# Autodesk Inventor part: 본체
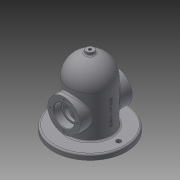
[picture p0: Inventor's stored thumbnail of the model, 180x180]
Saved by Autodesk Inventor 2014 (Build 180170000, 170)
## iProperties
Created: 2019-11
Part Number: 본체
Material: Generic
Document SubType Name: Modeling
Designer: OA55
Density: 1 g/cm^3
Appearance: Default
Author: OA55
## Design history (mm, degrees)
sketch "스케치1"
  geometry: C1 r 40 at (0, 0); 1 further point
  constraints: 1 centre point, 1 coincident
  dimensions: "d0" = 80 diameter of C1
extrude "돌출1" new body sketch "스케치1" distance "d1" = 80; taper "d2" = 0 deg
sketch "스케치2"
  geometry: C1 r 40 at (0, 0) reference; C2 r 70 at (0, 0)
  constraints: 1 centre point, 1 coincident
  dimensions: "d3" = 140 diameter of C2
extrude "돌출2" join sketch "스케치2" distance "d4" = 10; taper "d5" = 0 deg
node "작업 평면1"
sketch "스케치3"
  geometry: L1 (0, -40)-(0, -70) reference; L2 (0, -70)-(-10, -70) reference; L3 (-10, -70)-(-10, 70) reference; L4 (-10, 70)-(0, 70) reference; L5 (0, 70)-(0, 40) reference; L6 (0, 40)-(80, 40) reference; L7 (80, 40)-(80, -40) reference; L8 (80, -40)-(0, -40) reference; L9 (80, 0)-(120, 0); 2 further points; 1 other entity
  constraints: 4 end point, 1 coincident, 1 midpoint, 1 parallel, 1 vertical, 4 other
  dimensions: "d7" = 40 distance of L9.end L9.start
revolve "회전1" sketch "스케치3" stored, may be unused: angle "d8" = 90 deg
node "작업 평면2"
sketch "스케치4"
  geometry: L1 (-70, -10)-(70, -10) reference; C1 r 31 at (0, 40); 1 further point
  constraints: 1 centre point, 1 vertical alignment
  dimensions: "d10" = 62 diameter of C1; "d11" = 50 distance from line of C1.centre L1
extrude "돌출3" join sketch "스케치4" stored distance "d12" = 100; taper "d13" = 0 deg
sketch "스케치5"
  geometry: C1 r 31 at (0, 0) reference; C2 r 20 at (0, 0); 1 further point
  constraints: 1 centre point, 1 coincident
  dimensions: "d14" = 40 diameter of C2
extrude "돌출4" cut sketch "스케치5" distance "d15" = 15; taper "d16" = 0 deg
sketch "스케치6"
  geometry: C1 r 31 at (0, 0) reference; C2 r 20 at (0, 0); 1 further point
  constraints: 1 centre point, 1 coincident
  dimensions: "d17" = 40 diameter of C2
extrude "돌출5" cut sketch "스케치6" distance "d18" = 15; taper "d19" = 0 deg
sketch "스케치7"
  geometry: C1 r 20 at (0, 0) reference; C2 r 16.5 at (0, 0); 1 further point
  constraints: 1 centre point, 1 coincident
  dimensions: "d20" = 33 diameter of C2
extrude "돌출6" cut sketch "스케치7" stored distance "d21" = 15; taper "d22" = 0 deg
node "작업 평면5"
sketch "스케치10"
  geometry: C1 r 7.5 at (0, 0); 1 further point
  constraints: 1 centre point, 1 coincident
  dimensions: "d27" = 15 diameter of C1
extrude "돌출7" join sketch "스케치10" stored distance "d28" = 15; taper "d29" = 0 deg
node "작업 평면6"
sketch "스케치11"
  geometry: L1 (-70, -10)-(70, -10) reference; L2 (0, -10)-(0, 80); L3 (-30, -10)-(-30, 80); L4 (-30, 80)-(0, 80); 1 further point
  constraints: 6 end point, 2 perpendicular, 1 midpoint, 1 parallel, 1 point on line
  dimensions: "d31" = 90 distance of L2.start L2.end; "d32" = 60 diameter of L3 L2
revolve "회전2" sketch "스케치11" stored, may be unused: angle "d33" = 90 deg
sketch "스케치12"
  geometry: L1 (-30, 80)-(30, 80) reference; L2 (40, 0)-(40, 80) reference; L3 (30, 80)-(30, -10) reference; L4 (0, 80)-(0, 110); A1 r 40 centre (0, 80) between (40, 80) and (-40, 80) reference; 2 further points; 1 other entity
  constraints: 4 end point, 1 coincident, 1 horizontal, 1 parallel, 4 other
  dimensions: "d34" = 30 distance of L4.end L4.start
revolve "회전3" sketch "스케치12" stored, may be unused: angle "d35" = 90 deg
sketch "스케치13"
  geometry: C1 r 7.5 at (0, 0) reference; 1 further point
  constraints: 1 coincident
hole "구멍1" sketch "스케치13" at (0, 0) diameter "d36" = 5.188; stored, may be unused: countersink angle "d40" = 90 deg, drill point angle "d42" = 0 deg; dims "d37" = 15, "d38" = 4, "d39" = 2, "d41" = 15
sketch "스케치14"
  geometry: L1 (0, 0)-(-55, 0); L2 (0, 0)-(55, 0); C1 r 40 at (0, 0) reference; C2 r 4.5 at (55, 0); C3 r 4.5 at (-55, 0); A1 r 55 centre (0, 0) between (-55, 0) and (55, 0)
  constraints: 4 end point, 3 centre point, 3 coincident, 2 point on circle, 1 collinear, 1 horizontal
  dimensions: "d43" = 110 diameter of A1; "d44" = 9 diameter of C2; "d45" = 9 diameter of C3
extrude "돌출8" cut sketch "스케치14" stored distance "d46" = 15; taper "d47" = 0 deg
node "작업 평면7"
sketch "스케치15"
  geometry: L1 (-10, 70)-(-10, -70) reference; 2 further points
  constraints: 1 horizontal alignment, 1 other
  dimensions: "d48" = 50 distance from line of L1 point (40, 0)
feature "엠보싱1" sketch "스케치15" dims "d2" = 0, "d49" = 0.5, "d50" = 0
sketch "스케치17" dims "d52" = 52
  geometry: L1 (0, 0)-(0, 26); C1 r 31 at (0, 0) reference; 2 further points
  constraints: 2 coincident, 2 end point, 1 vertical, 1 vertical alignment, 2 other
hole "구멍2" sketch "스케치17" at (0, 26) diameter "d53" = 3.242; stored, may be unused: countersink angle "d57" = 90 deg, drill point angle "d59" = 118 deg; dims "d54" = 8, "d55" = 4, "d56" = 2, "d58" = 10
node "작업 평면9"
fillet "모깎기1" dims "d63" = 3
chamfer "모따기1" distance "d64" = 1; stored, may be unused: second distance "d65" = 2, angle "d66" = 45 deg
fillet "모깎기2" dims "d67" = 0.3
node "솔리드1"
pattern_circular "원형 패턴1" dims angle "d61" = 360 deg
mirror "대칭1"
node "절단 모서리 투영1"
other parameters: "d6" = 0, "d9" = 0, "d26" = -135, "d30" = 0
